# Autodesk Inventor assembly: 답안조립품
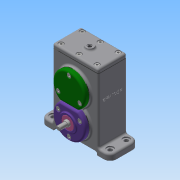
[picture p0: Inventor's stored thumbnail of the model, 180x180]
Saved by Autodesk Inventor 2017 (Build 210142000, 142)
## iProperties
Part Number: 답안조립품
Material: 일반
Document SubType Name: Assembly
Designer: 222
Author: 222
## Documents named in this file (24)
- C:\Users\222\Desktop\600506V1020\답안조립품.iam
- C:\Users\222\Desktop\600506V1020\본체.ipt
- C:\Users\222\Desktop\600506V1020\Ű 4 x 4 x 12.ipt
- C:\Users\222\Desktop\600506V1020\Ű 5 x 5 x 12.ipt
- C:\Users\222\Desktop\600506V1020\개스킷 A.ipt
- C:\Users\222\Desktop\600506V1020\개스킷 B.ipt
- C:\Users\222\Desktop\600506V1020\개스킷 C.ipt
- C:\Users\222\Desktop\600506V1020\베어링 6001.ipt
- 베어링 6001.ipt
- C:\Users\222\Desktop\600506V1020\베어링 6002.ipt
- 베어링 6002.ipt
- C:\Users\222\Desktop\600506V1020\볼트 M4.ipt
- C:\Users\222\Desktop\600506V1020\스퍼기어 A.ipt
- C:\Users\222\Desktop\600506V1020\스퍼기어 B.ipt
- C:\Users\222\Desktop\600506V1020\오일 실 10 20 7.ipt
- C:\Users\222\Desktop\600506V1020\오일 실 12 22 7.ipt
- C:\Users\222\Desktop\600506V1020\축 A.ipt
- C:\Users\222\Desktop\600506V1020\축 B.ipt
- C:\Users\222\Desktop\600506V1020\칼라.ipt
- C:\Users\222\Desktop\600506V1020\커버 A.ipt
- C:\Users\222\Desktop\600506V1020\커버 B.ipt
- C:\Users\222\Desktop\600506V1020\커버 C.ipt
- C:\Users\222\Desktop\600506V1020\커버 D.ipt
- C:\Users\222\Desktop\600506V1020\커버 E.ipt
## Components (7 placed, 5 different names)
1. Ű 4 x 4 x 12:1
2. 개스킷 A:1
3. 개스킷 B:1
4. 개스킷 C:1
5. 개스킷 B:2
6. 개스킷 B:3
7. Ű 5 x 5 x 12:1
